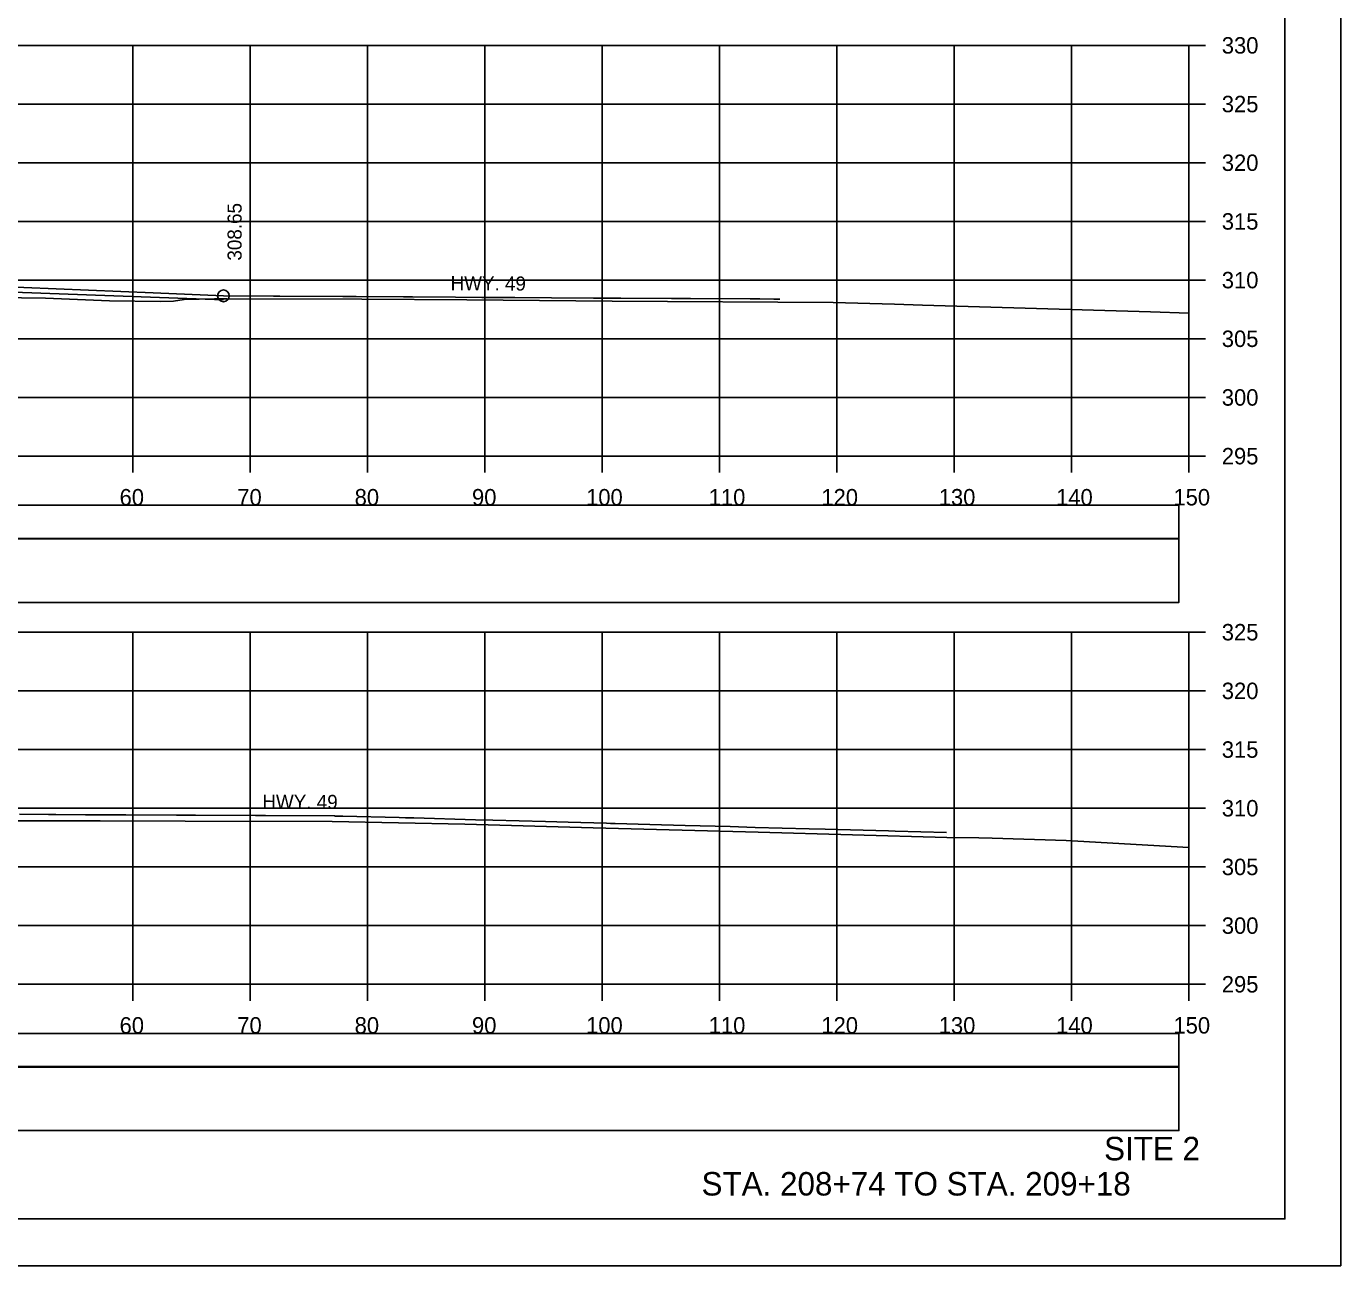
# Model space of a CAD drawing. Extents: x 1368122 to 1710785, y 373130 to 557566.
# Drawn here: x 1370073.2 to 1370185.2, y 374837 to 374942.6 of the extents above; entities that cross this region are included whole.
import ezdxf

# ---------------------------------------------------------------- set-up
doc = ezdxf.new("R2010")
doc.units = 0
for name, color, linetype in [('R_Alt Surface', 7, 'Continuous'), ('R_Axis', 7, 'Continuous'), ('R_Axis Annot', 7, 'Continuous'), ('R_Border', 7, 'Continuous'), ('R_Draft', 7, 'Continuous'), ('R_Exist Surface', 7, 'Continuous'), ('R_Fin Surface', 7, 'Continuous'), ('R_Grid', 7, 'Continuous'), ('R_No Plot', 7, 'Continuous'), ('R_Xsect Elev', 7, 'Continuous')]:
    doc.layers.add(name, color=color, linetype=linetype)

msp = doc.modelspace()

# ---------------------------------------------------------------- linework, layer by layer
for points in [[(1369873.09, 374899), (1370171.39, 374899), (1370171.39, 374901.82), (1369873.09, 374901.82)], [(1369873.09, 374893.54), (1370171.39, 374893.54), (1370171.39, 374898.95), (1369873.09, 374898.95)], [(1369873.09, 374854), (1370171.39, 374854), (1370171.39, 374856.82), (1369873.09, 374856.82)], [(1369873.09, 374848.54), (1370171.39, 374848.54), (1370171.39, 374853.95), (1369873.09, 374853.95)]]:
    msp.add_lwpolyline(points, close=True)
at = {"layer": 'R_Alt Surface'}
msp.add_lwpolyline([(1370089.97, 374919.34), (1370022.24, 374921.8), (1370006.85, 374921.5), (1370006.85, 374920.5), (1369992.24, 374920.2), (1369989.74, 374920.15), (1369989.74, 374920.65), (1369990.74, 374920.67), (1369990.74, 374922.01)], dxfattribs=at)
at = {"layer": 'R_Axis'}
for p, q in [((1370172.24, 374906.01), (1370172.24, 374941.01)), ((1370173.64, 374941.01), (1370172.24, 374941.01)), ((1370173.64, 374936.01), (1370172.24, 374936.01)), ((1370173.64, 374931.01), (1370172.24, 374931.01)), ((1370173.64, 374926.01), (1370172.24, 374926.01)), ((1370173.64, 374921.01), (1370172.24, 374921.01)), ((1370173.64, 374916.01), (1370172.24, 374916.01)), ((1370173.64, 374911.01), (1370172.24, 374911.01)), ((1369872.24, 374906.01), (1370172.24, 374906.01)), ((1370082.24, 374904.61), (1370082.24, 374906.01)), ((1370092.24, 374904.61), (1370092.24, 374906.01)), ((1370102.24, 374904.61), (1370102.24, 374906.01)), ((1370112.24, 374904.61), (1370112.24, 374906.01)), ((1370122.24, 374904.61), (1370122.24, 374906.01)), ((1370132.24, 374904.61), (1370132.24, 374906.01)), ((1370142.24, 374904.61), (1370142.24, 374906.01)), ((1370152.24, 374904.61), (1370152.24, 374906.01)), ((1370162.24, 374904.61), (1370162.24, 374906.01)), ((1370172.24, 374904.61), (1370172.24, 374906.01)), ((1370173.64, 374906.01), (1370172.24, 374906.01)), ((1370172.24, 374861.01), (1370172.24, 374891.01)), ((1370173.64, 374891.01), (1370172.24, 374891.01)), ((1370173.64, 374886.01), (1370172.24, 374886.01)), ((1370173.64, 374881.01), (1370172.24, 374881.01)), ((1370173.64, 374876.01), (1370172.24, 374876.01)), ((1370173.64, 374871.01), (1370172.24, 374871.01)), ((1370173.64, 374866.01), (1370172.24, 374866.01)), ((1369872.24, 374861.01), (1370172.24, 374861.01)), ((1370082.24, 374859.61), (1370082.24, 374861.01)), ((1370092.24, 374859.61), (1370092.24, 374861.01)), ((1370102.24, 374859.61), (1370102.24, 374861.01)), ((1370112.24, 374859.61), (1370112.24, 374861.01)), ((1370122.24, 374859.61), (1370122.24, 374861.01)), ((1370132.24, 374859.61), (1370132.24, 374861.01)), ((1370142.24, 374859.61), (1370142.24, 374861.01)), ((1370152.24, 374859.61), (1370152.24, 374861.01)), ((1370162.24, 374859.61), (1370162.24, 374861.01)), ((1370172.24, 374859.61), (1370172.24, 374861.01)), ((1370173.64, 374861.01), (1370172.24, 374861.01))]:
    msp.add_line(p, q, dxfattribs=at)
at = {"layer": 'R_Border'}
for q in [(1370180.42, 375046.47), (1369864.24, 374841.01)]:
    msp.add_line((1370180.42, 374841.01), q, dxfattribs=at)
at = {"layer": 'R_Exist Surface'}
for points in [[(1370068.62, 374919.56), (1370074.8, 374919.47), (1370080.26, 374919.24), (1370084.61, 374919.2), (1370085.71, 374919.21), (1370086.61, 374919.35), (1370089.21, 374919.4), (1370090.25, 374919.42), (1370101.76, 374919.38), (1370110.7, 374919.32), (1370123.08, 374919.22), (1370141.93, 374919.1), (1370147.15, 374918.96), (1370149.55, 374918.88), (1370168.96, 374918.3), (1370172.24, 374918.2)], [(1370066.45, 374874.95), (1370079.46, 374874.93), (1370086.7, 374874.91), (1370099.23, 374874.89), (1370110.53, 374874.65), (1370121.47, 374874.35), (1370135.54, 374873.96), (1370151.61, 374873.53), (1370154.33, 374873.49), (1370155.48, 374873.47), (1370161.78, 374873.25), (1370172.24, 374872.67)]]:
    msp.add_lwpolyline(points, dxfattribs=at)
at = {"layer": 'R_Fin Surface'}
for points in [[(1370070.19, 374920.49), (1370083.98, 374919.92), (1370089.97, 374919.67)], [(1370089.97, 374919.67), (1370094.23, 374919.64), (1370094.77, 374919.64), (1370100.15, 374919.61), (1370101.27, 374919.6), (1370105.31, 374919.58), (1370105.32, 374919.58), (1370105.32, 374919.58), (1370105.32, 374919.58), (1370105.33, 374919.58), (1370105.55, 374919.58), (1370106.07, 374919.57), (1370109.75, 374919.55), (1370111.99, 374919.54), (1370114.81, 374919.52), (1370117.92, 374919.5), (1370121.49, 374919.48), (1370123.84, 374919.47), (1370128.16, 374919.44), (1370129.76, 374919.43), (1370134.84, 374919.4), (1370135.68, 374919.4), (1370136.88, 374919.39), (1370137.01, 374919.39), (1370137.01, 374919.39), (1370137.02, 374919.39), (1370137.05, 374919.39), (1370137.38, 374919.39)], [(1370072.58, 374875.49), (1370075.06, 374875.48), (1370075.38, 374875.48), (1370075.68, 374875.48), (1370078.22, 374875.46), (1370081.64, 374875.44), (1370085.96, 374875.42), (1370087.6, 374875.41), (1370092.7, 374875.38), (1370093.56, 374875.38), (1370099.44, 374875.35), (1370099.52, 374875.34), (1370099.58, 374875.34), (1370100.14, 374875.34), (1370104.93, 374875.21), (1370105.48, 374875.2), (1370106.18, 374875.18), (1370111.44, 374875.03), (1370112.92, 374874.99), (1370117.4, 374874.87), (1370119.34, 374874.82), (1370122.6, 374874.73), (1370122.6, 374874.73), (1370122.61, 374874.73), (1370122.61, 374874.73), (1370122.61, 374874.73), (1370122.94, 374874.72), (1370123.36, 374874.71), (1370126.29, 374874.63), (1370129.32, 374874.54), (1370133.15, 374874.44), (1370135.28, 374874.38), (1370139.89, 374874.26), (1370141.24, 374874.22), (1370146.63, 374874.07), (1370147.2, 374874.06), (1370151.58, 374873.94)]]:
    msp.add_lwpolyline(points, dxfattribs=at)
at = {"layer": 'R_Grid'}
for p, q in [((1369872.24, 374941.01), (1370172.24, 374941.01)), ((1370082.24, 374906.01), (1370082.24, 374941.01)), ((1370092.24, 374906.01), (1370092.24, 374941.01)), ((1370102.24, 374906.01), (1370102.24, 374941.01)), ((1370112.24, 374906.01), (1370112.24, 374941.01)), ((1370122.24, 374906.01), (1370122.24, 374941.01)), ((1370132.24, 374906.01), (1370132.24, 374941.01)), ((1370142.24, 374906.01), (1370142.24, 374941.01)), ((1370152.24, 374906.01), (1370152.24, 374941.01)), ((1370162.24, 374906.01), (1370162.24, 374941.01)), ((1370172.24, 374906.01), (1370172.24, 374941.01)), ((1369872.24, 374936.01), (1370172.24, 374936.01)), ((1369872.24, 374931.01), (1370172.24, 374931.01)), ((1369872.24, 374926.01), (1370172.24, 374926.01)), ((1369872.24, 374921.01), (1370172.24, 374921.01)), ((1369872.24, 374916.01), (1370172.24, 374916.01)), ((1369872.24, 374911.01), (1370172.24, 374911.01)), ((1369872.24, 374906.01), (1370172.24, 374906.01)), ((1369872.24, 374891.01), (1370172.24, 374891.01)), ((1370082.24, 374861.01), (1370082.24, 374891.01)), ((1370092.24, 374861.01), (1370092.24, 374891.01)), ((1370102.24, 374861.01), (1370102.24, 374891.01)), ((1370112.24, 374861.01), (1370112.24, 374891.01)), ((1370122.24, 374861.01), (1370122.24, 374891.01)), ((1370132.24, 374861.01), (1370132.24, 374891.01)), ((1370142.24, 374861.01), (1370142.24, 374891.01)), ((1370152.24, 374861.01), (1370152.24, 374891.01)), ((1370162.24, 374861.01), (1370162.24, 374891.01)), ((1370172.24, 374861.01), (1370172.24, 374891.01)), ((1369872.24, 374886.01), (1370172.24, 374886.01)), ((1369872.24, 374881.01), (1370172.24, 374881.01)), ((1369872.24, 374876.01), (1370172.24, 374876.01)), ((1369872.24, 374871.01), (1370172.24, 374871.01)), ((1369872.24, 374866.01), (1370172.24, 374866.01)), ((1369872.24, 374861.01), (1370172.24, 374861.01))]:
    msp.add_line(p, q, dxfattribs=at)
at = {"layer": 'R_No Plot'}
msp.add_line((1369851.84, 374837.03), (1370185.17, 374837.03), dxfattribs=at)
for points in [[(1369851.83, 375050.37), (1370185.17, 375050.37), (1370185.17, 374837.03), (1369851.83, 374837.03)], [(1370098.16, 375046.47), (1370117.78, 375046.47), (1370117.78, 375036.59), (1370133.89, 375036.59), (1370157.09, 375036.59), (1370157.21, 375008.44), (1370180.42, 375008.44), (1370180.42, 374841.01), (1369864.24, 374841.01), (1369864.24, 375046.47)]]:
    msp.add_lwpolyline(points, close=True, dxfattribs=at)
msp.add_circle((1370089.97, 374919.67), 0.5, dxfattribs=at)

# ---------------------------------------------------------------- texts
at = {"layer": 'R_Axis Annot'}
for s, p in [('330', (1370175.04, 374940.31)), ('325', (1370175.04, 374935.31)), ('320', (1370175.04, 374930.31)), ('315', (1370175.04, 374925.31)), ('310', (1370175.04, 374920.31)), ('305', (1370175.04, 374915.31)), ('300', (1370175.04, 374910.31)), ('295', (1370175.04, 374905.31)), ('60', (1370081.12, 374901.81)), ('70', (1370091.15, 374901.81)), ('80', (1370101.15, 374901.81)), ('90', (1370111.15, 374901.81)), ('100', (1370120.87, 374901.81)), ('110', (1370131.32, 374901.81)), ('120', (1370140.92, 374901.81)), ('130', (1370150.92, 374901.81)), ('140', (1370160.92, 374901.81)), ('150', (1370170.92, 374901.81)), ('325', (1370175.04, 374890.31)), ('320', (1370175.04, 374885.31)), ('315', (1370175.04, 374880.31)), ('310', (1370175.04, 374875.31)), ('305', (1370175.04, 374870.31)), ('300', (1370175.04, 374865.31)), ('295', (1370175.04, 374860.31)), ('60', (1370081.12, 374856.81)), ('70', (1370091.15, 374856.81)), ('80', (1370101.15, 374856.81)), ('90', (1370111.15, 374856.81)), ('100', (1370120.87, 374856.81)), ('110', (1370131.32, 374856.81)), ('120', (1370140.92, 374856.81)), ('130', (1370150.92, 374856.81)), ('140', (1370160.92, 374856.81)), ('150', (1370170.92, 374856.81))]:
    msp.add_text(s, height=1.4, dxfattribs=at).set_placement(p)
at = {"layer": 'R_Draft'}
for s, p in [('SITE 2', (1370165.01, 374846.01)), ('STA. 208+74 TO STA. 209+18', (1370130.71, 374843.01))]:
    msp.add_text(s, height=2, dxfattribs=at).set_placement(p)
at = {"layer": 'R_Fin Surface'}
for rotation, p in [(359.6657, (1370109.32, 374920.15)), (359.6818, (1370093.28, 374875.98))]:
    msp.add_text('HWY. 49', height=1.2, rotation=rotation, dxfattribs=at).set_placement(p)
at = {"layer": 'R_Xsect Elev'}
msp.add_text('308.65', height=1.2, rotation=90, dxfattribs=at).set_placement((1370091.52, 374922.67))

doc.saveas('drawing.dxf')
